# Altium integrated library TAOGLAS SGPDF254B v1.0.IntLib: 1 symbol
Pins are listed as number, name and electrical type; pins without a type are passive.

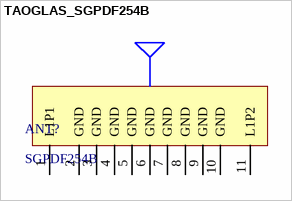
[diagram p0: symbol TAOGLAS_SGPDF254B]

## TAOGLAS_SGPDF254B
designator ANT?, comment SGPDF254B
GPS/GLONASS/GALILEO/BEIDOU Dual Feed 25*25*4mm Ceramic Patch SMD Antenna; ComponentLibStatus: Created; MFG: Taoglas; Temp_High: +85C; Temp_Low: -40C
footprint TAOGLAS_SGPDF254B (GPS/GLONASS/GALILEO/BEIDOU Dual Feed 25*25*4mm Ceramic Patch SMD Antenna)
pins: 1 L1P1, 2 GND, 3 GND, 4 GND, 5 GND, 6 GND, 7 GND, 8 GND, 9 GND, 10 GND, 11 L1P2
